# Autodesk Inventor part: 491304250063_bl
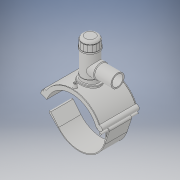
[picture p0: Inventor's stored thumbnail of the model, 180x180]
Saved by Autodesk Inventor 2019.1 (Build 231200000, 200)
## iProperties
Created: 2017-07
Part Number: 491304250063_bl
Material: Generic
Description: PLASSON TAPPING TEE SADDLE 250mm x 63mm
Document SubType Name: Modeling
Designer: KIM
Mass: 1712.7 g
Surface Area: 2671.49 cm^2
Volume: 1712.7 cm^3
Density: 1 g/cm^3
Appearance: Default
Author: KIM
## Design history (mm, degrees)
derived "491304.ipt"
feature "Solid1::491304.ipt" dims "ScaleForDerivedMember" = 10
feature "Solid2::491304.ipt" dims "ScaleForDerivedMember" = 10
feature "Solid4::491304.ipt" dims "ScaleForDerivedMember" = 10
feature "Solid5::491304.ipt" dims "ScaleForDerivedMember" = 10
tag "TaggingFeature1"
body "Solid1"
body "Solid2"
other parameters: "d1" = 101.118 [user parameter], "d2" = 288 [user parameter], "d3" = 62.5 [user parameter], "d4" = 176 [user parameter], "d5" = 0 [user parameter], "d6" = 0.1 [user parameter], "d8" = 0 [user parameter], "d41" = 97.65 [user parameter], "d43" = 0 [user parameter], "d45" = 0 [user parameter], "d47" = 156.159 [user parameter], "d79" = 15 [user parameter], "d80" = 70.4 [user parameter], "d82" = 5 deg [user parameter], "d84" = 4 [user parameter], "d85" = 14 [user parameter], "d86" = 0 [user parameter], "d87" = 3 [user parameter], "d88" = 0 [user parameter], "d97" = 3.52 [user parameter], "d98" = 0 [user parameter], "d102" = 2.5 [user parameter], "d120" = 140 deg [user parameter], "d123" = 606.708 [user parameter], "d126" = 0 [user parameter], "d153" = 176 [user parameter], "d154" = 0 [user parameter], "d159" = -29.7764 [user parameter], "d162" = 105.6 [user parameter], "d163" = 0 [user parameter], "d164" = 125 [user parameter], "d169" = 4.0905 [user parameter], "d172" = 0 [user parameter], "d173" = 1 [user parameter], "d175" = 125 [user parameter], "d176" = 20 deg [user parameter], "d177" = 17.5 [user parameter], "d180" = 0 [user parameter], "d184" = 14 [user parameter], "d187" = 137.5 [user parameter], "d188" = 15 [user parameter], "d189" = 17.5 [user parameter], "d190" = 0 [user parameter], "d191" = 187.5 [user parameter], "d195" = 90 deg [user parameter], "d197" = 0 [user parameter], "d199" = 0 [user parameter], "d200" = 17.5 [user parameter], "d202" = 0 [user parameter], "d203" = 195 [user parameter], "d206" = 75.6 [user parameter], "d207" = 146.25 [user parameter], "d208" = 152.1 [user parameter], "d209" = 181.35 [user parameter], "d210" = 76.86 [user parameter], "d212" = 72.45 [user parameter], "d213" = 39.15 [user parameter], "d216" = 0 [user parameter], "d217" = 25 [user parameter], "d218" = 12.5 [user parameter], "d219" = 2.5 [user parameter], "d224" = 0 [user parameter], "d259" = 50.4 [user parameter], "d260" = 63 [user parameter], "d265" = 0 [user parameter], "d267" = 13.00006 [user parameter], "d268" = 2.60001 [user parameter], "d269" = 2.60001 [user parameter], "d271" = 2.60001 [user parameter], "d273" = 0 [user parameter], "d274" = 23.56194 [user parameter], "d280" = 0 [user parameter], "d283" = 0 [user parameter], "d285" = 0 [user parameter], "d290" = 25 [user parameter], "d293" = 137.5 [user parameter], "d294" = 128.75 [user parameter], "d296" = 37.5 [user parameter], "d299" = 75 [user parameter], "d300" = 3 [user parameter], "d301" = 5 [user parameter], "d303" = 81.9 [user parameter], "d304" = 69.3 [user parameter], "d305" = 45 deg [user parameter], "d306" = 50.4 [user parameter], "d307" = 156.25 [user parameter], "d310" = 1 [user parameter], "L" = 176 [user parameter], "d_t" = 6 [user parameter], "H2" = 195 [user parameter], "H1" = 75 [user parameter], "d_1" = 63 [user parameter]
